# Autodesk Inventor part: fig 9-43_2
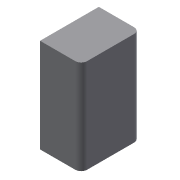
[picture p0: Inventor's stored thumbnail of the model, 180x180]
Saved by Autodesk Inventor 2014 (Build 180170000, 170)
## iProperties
Created: 2013-03
Part Number: fig 9-43_2
Material: Generic
Document SubType Name: Modeling
Designer: CADCIM
Density: 1 g/cm^3
Appearance: Default
Author: CADCIM
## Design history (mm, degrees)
sketch "Sketch1"
  geometry: L1 (-2.508, 1.862)-(2.492, 1.862); L2 (2.492, 1.862)-(2.492, -6.138); L3 (2.492, -6.138)-(-2.508, -6.138); L4 (-2.508, -6.138)-(-2.508, 1.862); 1 further point
  constraints: 8 end point, 2 parallel, 1 horizontal, 1 perpendicular
  dimensions: "d0" = 5 distance of L1.start L1.end; "d2" = 8 distance of L1.end L2.end
extrude "Extrusion1" new body sketch "Sketch1" distance "d3" = 3.5; taper "d4" = 0 deg
fillet "Fillet1" dims "d5" = 0.5
fillet "Fillet2" dims "d6" = 0.5
body "Solid1"
